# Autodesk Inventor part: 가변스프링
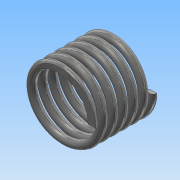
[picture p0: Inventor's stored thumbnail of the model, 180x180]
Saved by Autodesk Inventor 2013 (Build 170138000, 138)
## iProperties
Created: 2019-07
Part Number: 가변스프링
Material: 강철, 탄소
Document SubType Name: Modeling
Designer: Administrator
Density: 7.87 g/cm^3
Mass: 7.71262 g
Surface Area: 19.9888 cm^2
Volume: 0.980003 cm^3
Author: Administrator
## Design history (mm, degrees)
sketch "스케치1"
  geometry: L1 (0, 0)-(0, 16); L2 (0, 16)-(16.881, 16); C1 r 1 at (8.5, 0)
  constraints: 4 end point, 1 centre point, 1 horizontal alignment, 1 perpendicular, 1 vertical
  dimensions: "d0" = 16 distance of L1.start L1.end (derived); "d1" = 2 diameter of C1; "d2" = 17 diameter of C1.centre L1
feature "코일1" sketch "스케치1" pitch "d3" = 10; turns "d5" = 6; dims "d4" = 16 (= d0), "d6" = 0, angle "d7" = 90 deg, angle "d8" = 90 deg, "d9" = 0, "d10" = 0
sketch "스케치2"
  geometry: L1 (0, 12.5)-(16, 12.5); L2 (16, 12.5)-(16, -12.5); L3 (16, -12.5)-(0, -12.5); L4 (0, -12.5)-(0, 12.5); 2 further points
  constraints: 8 end point, 2 parallel, 1 coincident, 1 horizontal, 1 midpoint, 1 perpendicular
  dimensions: "d11" = 16 distance between parallel lines of L2 L4 (derived); "d13" = 25 distance between parallel lines of L1 L3
extrude "돌출1" sketch "스케치2" stored distance "d14" = 50; taper "d15" = 0 deg
node "솔리드1"
